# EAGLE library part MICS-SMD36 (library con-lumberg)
CONNECTOR
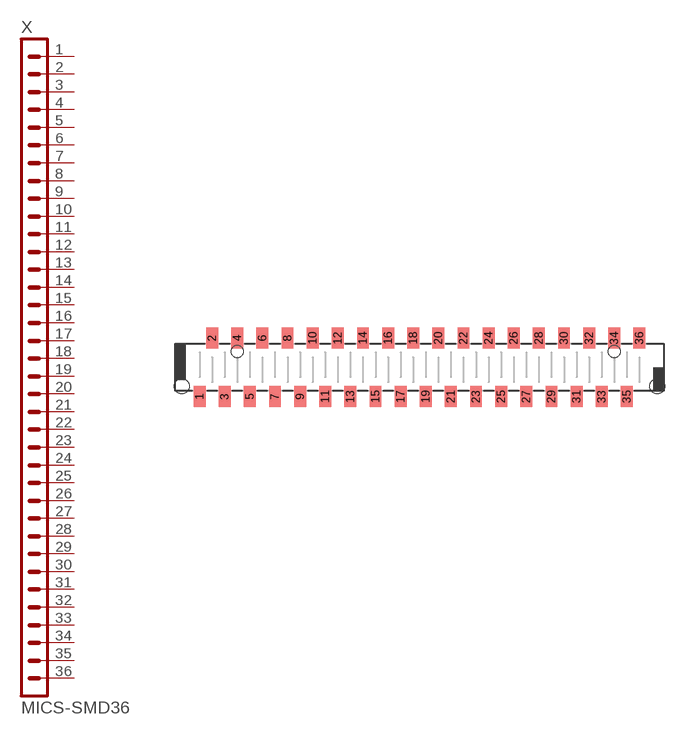
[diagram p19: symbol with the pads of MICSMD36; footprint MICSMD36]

Designator prefix X

## MICS-SMD36 (OC_FARNELL: unknown; OC_NEWARK: unknown)  [MICSMD36]
1  1  pas
2  2  pas
3  3  pas
4  4  pas
5  5  pas
6  6  pas
7  7  pas
8  8  pas
9  9  pas
10  10  pas
11  11  pas
12  12  pas
13  13  pas
14  14  pas
15  15  pas
16  16  pas
17  17  pas
18  18  pas
19  19  pas
20  20  pas
21  21  pas
22  22  pas
23  23  pas
24  24  pas
25  25  pas
26  26  pas
27  27  pas
28  28  pas
29  29  pas
30  30  pas
31  31  pas
32  32  pas
33  33  pas
34  34  pas
35  35  pas
36  36  pas

## Footprint MICSMD36 (pad centres in mm)
CONNECTOR
smd 1.2 x 2.1: 1 -22.225,-2.959; 2 -20.955,2.959; 3 -19.685,-2.959; 4 -18.415,2.959; 5 -17.145,-2.959; 6 -15.875,2.959; 7 -14.605,-2.959; 8 -13.335,2.959; 9 -12.065,-2.959; 10 -10.795,2.959; 11 -9.525,-2.959; 12 -8.255,2.959; 13 -6.985,-2.959; 14 -5.715,2.959; 15 -4.445,-2.959; 16 -3.175,2.959; 17 -1.905,-2.959; 18 -0.635,2.959; 19 0.635,-2.959; 20 1.905,2.959; 21 3.175,-2.959; 22 4.445,2.959; 23 5.715,-2.959; 24 6.985,2.959; 25 8.255,-2.959; 26 9.525,2.959; 27 10.795,-2.959; 28 12.065,2.959; 29 13.335,-2.959; 30 14.605,2.959; 31 15.875,-2.959; 32 17.145,2.959; 33 18.415,-2.959; 34 19.685,2.959; 35 20.955,-2.959; 36 22.225,2.959
hole 1.5 at 24.025,-1.912
hole 1.5 at -24.025,-1.912
hole 1.2 at -18.415,1.6
hole 1.2 at 19.685,1.6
